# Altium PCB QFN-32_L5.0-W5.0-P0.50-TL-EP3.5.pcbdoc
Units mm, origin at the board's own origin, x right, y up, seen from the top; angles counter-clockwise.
Board outline 18.78 x 18.5 mm, 2 copper layers (Top Layer, Bottom Layer), stack 0.07 mm thick; 1 components, 0 nets, 33 pads, 0 vias.
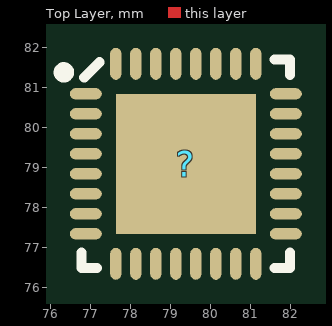
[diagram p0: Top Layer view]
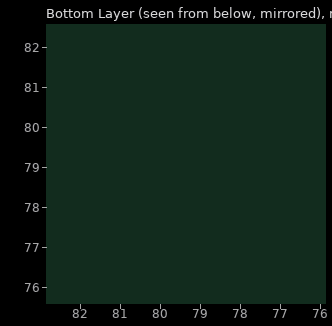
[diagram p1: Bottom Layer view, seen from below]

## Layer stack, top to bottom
Top Solder Mask Layer: solder mask 0.01, Dk 3.3
Top Layer: signal copper 0.035
Bottom Layer: signal copper 0.035
Bottom Solder Mask Layer: solder mask 0.01, Dk 3.3

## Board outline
88.625,69.85 69.85,69.85 69.85,88.35 88.625,88.35

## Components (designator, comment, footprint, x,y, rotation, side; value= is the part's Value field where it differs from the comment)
? "QFN-32_L5.0-W5.0-P0.50-TL-EP3.5" QFN-32_L5.0-W5.0-P0.50-TL-EP3.5 79.375,79.1 r0 top

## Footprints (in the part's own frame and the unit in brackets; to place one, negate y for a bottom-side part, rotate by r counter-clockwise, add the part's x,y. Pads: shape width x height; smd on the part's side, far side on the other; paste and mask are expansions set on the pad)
QFN-32_L5.0-W5.0-P0.50-TL-EP3.5 [mm]
  oval 0.8x0.28 smd paste-100 mask+0.051: 1(-2.5,1.75) 2(-2.5,1.25) 3(-2.5,0.75) 4(-2.5,0.25) 5(-2.5,-0.25) 6(-2.5,-0.75) 7(-2.5,-1.25) 8(-2.5,-1.75) 17(2.5,-1.75) 18(2.5,-1.25) 19(2.5,-0.75) 20(2.5,-0.25) 21(2.5,0.25) 22(2.5,0.75) 23(2.5,1.25) 24(2.5,1.75)
  oval 0.28x0.8 smd paste-100 mask+0.051: 9(-1.75,-2.5) 10(-1.25,-2.5) 11(-0.75,-2.5) 12(-0.25,-2.5) 13(0.25,-2.5) 14(0.75,-2.5) 15(1.25,-2.5) 16(1.75,-2.5) 25(1.75,2.5) 26(1.25,2.5) 27(0.75,2.5) 28(0.25,2.5) 29(-0.25,2.5) 30(-0.75,2.5) 31(-1.25,2.5) 32(-1.75,2.5)
  rect 3.5x3.5 smd paste-100 mask+0.051: 33(0,0)
  silkscreen extent -3.17,-2.6 2.6,2.6

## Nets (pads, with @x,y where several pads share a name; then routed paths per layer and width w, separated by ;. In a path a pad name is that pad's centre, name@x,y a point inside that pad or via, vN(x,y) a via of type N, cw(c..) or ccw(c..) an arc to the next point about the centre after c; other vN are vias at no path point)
pads on no net: ?.1 ?.2 ?.3 ?.4 ?.5 ?.6 ?.7 ?.8 ?.9 ?.10 ?.11 ?.12 ?.13 ?.14 ?.15 ?.16 ?.17 ?.18 ?.19 ?.20 ?.21 ?.22 ?.23 ?.24 ?.25 ?.26 ?.27 ?.28 ?.29 ?.30 ?.31 ?.32 ?.33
